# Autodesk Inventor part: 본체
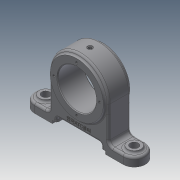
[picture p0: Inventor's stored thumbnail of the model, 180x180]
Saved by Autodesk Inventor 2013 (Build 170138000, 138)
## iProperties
Created: 2019-05
Part Number: 본체
Material: Generic
Document SubType Name: Modeling
Designer: user
Density: 1 g/cm^3
Author: user
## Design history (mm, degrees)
sketch "스케치1"
  geometry: C1 r 26 at (0, 0); C2 r 36 at (0, 0); 1 further point
  constraints: 2 centre point, 2 coincident
  dimensions: "d0" = 52 diameter of C1; "d3" = 72 diameter of C2
extrude "돌출1" new body sketch "스케치1" stored distance "d4" = 36; taper "d5" = 0 deg
node "작업 평면1"
sketch "스케치2"
  geometry: C1 r 40 at (0, 0); C2 r 36 at (0, 0); 1 further point
  constraints: 2 centre point, 2 coincident
  dimensions: "d6" = 80 diameter of C1; "d9" = 72 diameter of C2
extrude "돌출2" join sketch "스케치2" stored distance "d10" = 30; taper "d11" = 0 deg
fillet "모깎기1" dims "d12" = 3
sketch "스케치3" dims "d13" = 62
  geometry: L1 (0, 0)-(0, 31); C1 r 36 at (0, 0) reference; 1 further point
  constraints: 2 coincident, 2 end point, 1 vertical, 1 vertical alignment, 2 other
hole "구멍1" sketch "스케치3" at (0, 31) diameter "d15" = 3.242; stored, may be unused: countersink angle "d19" = 90 deg, drill point angle "d21" = 118 deg; dims "d16" = 6, "d17" = 4, "d18" = 2, "d20" = 8
node "작업 평면2"
node "작업 평면3"
node "작업 평면4"
sketch "스케치6"
  geometry: L1 (40, 0)-(40, -48); L2 (40, -48)-(75, -48); L3 (75, -48)-(75, -60); L4 (75, -60)-(36, -60); L5 (36, -60)-(36, -56); L6 (36, -56)-(30, -56); L7 (30, -56)-(30, -50); L8 (30, -50)-(0, -50); L9 (0, -50)-(0, 5.081); L10 (-40, 0)-(-40, -48); L11 (-40, -48)-(-75, -48); L12 (-75, -48)-(-75, -60); L13 (-75, -60)-(-36, -60); L14 (-36, -60)-(-36, -56); L15 (-36, -56)-(-30, -56); L16 (-30, -56)-(-30, -50); L17 (-30, -50)-(0, -50); C1 r 26 at (0, 0) reference; A1 r 40 centre (0, 0) between (-40, 0) and (40, 0); 2 further points
  constraints: 34 end point, 8 symmetric about line, 7 parallel, 2 point on circle, 2 vertical, 1 centre point, 1 coincident, 1 horizontal alignment, 1 perpendicular, 1 point on line, 1 other
  dimensions: "d39" = 100 dimension on L4; "d40" = 10 distance between parallel lines of L8 L4; "d41" = 60 diameter of L7 L9; "d43" = 72 diameter of L5 L9; "d44" = 12 distance of L2.end L3.end; "d45" = 4 distance of L4.end L5.end; "d46" = 150 diameter of L3 L9
extrude "돌출4" join sketch "스케치6" stored distance "d47" = 30; taper "d48" = 0 deg
sketch "스케치7"
  geometry: L1 (0, 0)-(0, 30) reference; L2 (0, 30)-(35, 30) reference; L3 (150, 0)-(150, 30) reference; L4 (115, 30)-(150, 30) reference; C1 r 9 at (15, 15); C2 r 9 at (135, 15); 1 further point
  constraints: 2 centre point, 1 equal radius
  dimensions: "d49" = 18 diameter of C1; "d51" = 15 distance from line of L2 C1.centre; "d53" = 15 distance from line of L4 C2.centre; "d54" = 120 distance of C1.centre C2.centre; "d55" = 15 distance from line of C1.centre L1
extrude "돌출5" join sketch "스케치7" distance "d56" = 3; taper "d57" = 0 deg
fillet "모깎기2" dims "d58" = 3
sketch "스케치8"
  geometry: C1 r 9 at (0, 0) reference; C2 r 5.5 at (0, 0); C3 r 9 at (120, 0) reference; C4 r 5.5 at (120, 0); 1 further point
  constraints: 2 centre point, 2 coincident
  dimensions: "d59" = 11 diameter of C2; "d61" = 11 diameter of C4
extrude "돌출6" cut sketch "스케치8" stored distance "d62" = 3; taper "d63" = 0 deg
chamfer "모따기1" distance "d64" = 1; stored, may be unused: second distance "d65" = 2, angle "d66" = 45 deg
fillet "모깎기3" dims "d67" = 15
fillet "모깎기4" dims "d68" = 6
fillet "모깎기5" dims "d69" = 3
fillet "모깎기6" dims "d70" = 3
fillet "모깎기7" dims "d71" = 3
sketch "스케치9"
  geometry: L1 (-27, -50)-(27, -50) reference; L2 (0, 0)-(0, -61.39); A1 r 39 centre (0, 0) between (-37, -12.329) and (37, -12.329) reference; 1 further point
  constraints: 2 end point, 1 perpendicular, 1 point on line, 1 other
  dimensions: "d72" = 7 distance from line of L1 point (0, -43)
extrude "돌출7" join sketch "스케치9" distance "d73" = 0.5; taper "d74" = 0 deg
sketch "스케치10"
  geometry: C1 r 1.5 at (0, 26); 1 further point
  constraints: 1 centre point, 1 vertical alignment, 1 other
  dimensions: "d77" = 3 diameter of C1
extrude "돌출8" cut sketch "스케치10" stored distance "d79" = 12; taper "d80" = 0 deg
node "작업 평면5"
sketch "스케치11"
  geometry: 1 further point
hole "구멍3" sketch "스케치11" at (0, 0) diameter "d81" = 4.917; stored, may be unused: countersink angle "d85" = 90 deg, drill point angle "d87" = 118 deg; dims "d82" = 7, "d83" = 7, "d84" = 1, "d86" = 9
sketch "스케치12"
  geometry: C1 r 1 at (0, 0); 1 further point
  constraints: 1 centre point, 1 coincident
  dimensions: "d88" = 2 diameter of C1
extrude "돌출9" cut sketch "스케치12" stored distance "d90" = 12; taper "d91" = 0 deg
node "솔리드1"
pattern_circular "원형 패턴1" dims angle "d23" = 360 deg
mirror "대칭1"
node "투영된 루프1"
